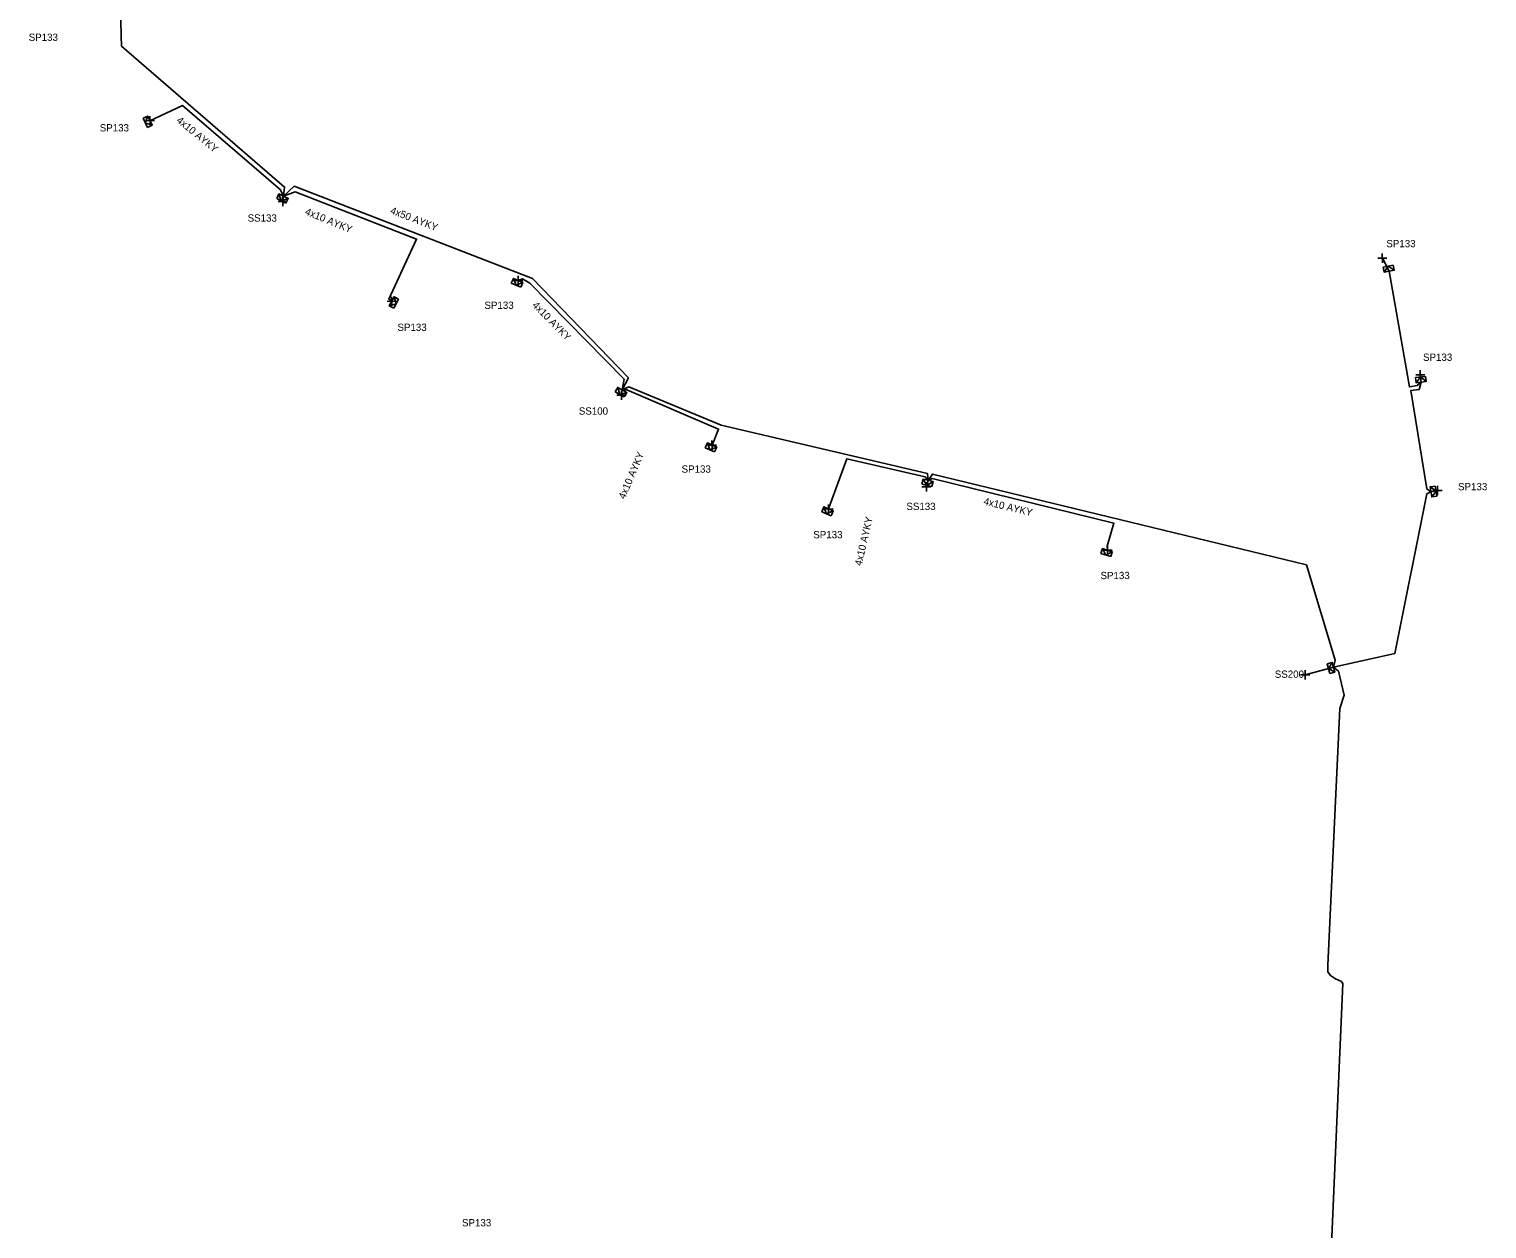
# Model space of a CAD drawing. Extents: x -762503 to -762212, y -1153994 to -1153331.
# Drawn here: x -762411.4 to -762212.4, y -1153826.1 to -1153662.2 of the extents above; entities that cross this region are included whole.
import ezdxf

# ---------------------------------------------------------------- set-up
doc = ezdxf.new("R2010")
doc.units = 0
for name, color, linetype in [('Vrstva 31', 7, 'Continuous'), ('Vrstva 33', 7, 'Continuous'), ('Vrstva 34', 7, 'Continuous'), ('Vrstva 5', 7, 'Continuous'), ('Vrstva 52', 7, 'Continuous'), ('Vrstva 54', 7, 'Continuous'), ('Vrstva 59', 7, 'Continuous'), ('Vrstva 6', 7, 'Continuous')]:
    doc.layers.add(name, color=color, linetype=linetype)

msp = doc.modelspace()

# ---------------------------------------------------------------- linework, layer by layer
at = {"layer": 'Vrstva 31'}
for points in [[(-762395.881, -1153674.399), (-762395.247, -1153674.103), (-762394.655, -1153675.372), (-762395.29, -1153675.668)], [(-762395.881, -1153674.399), (-762395.29, -1153675.668)], [(-762395.586, -1153675.034), (-762395.247, -1153674.103)], [(-762395.586, -1153675.034), (-762394.655, -1153675.372)], [(-762377.639, -1153685.382), (-762377.332, -1153684.752), (-762376.073, -1153685.366), (-762376.38, -1153685.995)], [(-762377.01, -1153685.688), (-762377.332, -1153684.752)], [(-762377.639, -1153685.382), (-762376.38, -1153685.995)], [(-762377.01, -1153685.688), (-762376.073, -1153685.366)], [(-762225.139, -1153694.488), (-762226.518, -1153694.732)], [(-762225.139, -1153694.488), (-762225.018, -1153695.178), (-762226.397, -1153695.421), (-762226.518, -1153694.732)], [(-762225.829, -1153694.61), (-762226.397, -1153695.421)], [(-762225.829, -1153694.61), (-762225.018, -1153695.178)], [(-762345.597, -1153696.934), (-762345.312, -1153696.294), (-762344.033, -1153696.864), (-762344.318, -1153697.503)], [(-762345.597, -1153696.934), (-762344.318, -1153697.503)], [(-762344.957, -1153697.219), (-762345.312, -1153696.294)], [(-762344.957, -1153697.219), (-762344.033, -1153696.864)], [(-762361.652, -1153700.37), (-762362.27, -1153700.041), (-762361.612, -1153698.805), (-762360.994, -1153699.134)], [(-762361.652, -1153700.37), (-762360.994, -1153699.134)], [(-762361.323, -1153699.752), (-762361.612, -1153698.805)], [(-762361.323, -1153699.752), (-762362.27, -1153700.041)], [(-762331.405, -1153711.792), (-762331.065, -1153711.18), (-762329.841, -1153711.858), (-762330.18, -1153712.471)], [(-762330.793, -1153712.131), (-762331.065, -1153711.18)], [(-762220.737, -1153709.669), (-762222.127, -1153709.84)], [(-762220.737, -1153709.669), (-762220.652, -1153710.364), (-762222.042, -1153710.535), (-762222.127, -1153709.84)], [(-762221.432, -1153709.755), (-762222.042, -1153710.535)], [(-762221.432, -1153709.755), (-762220.652, -1153710.364)], [(-762331.405, -1153711.792), (-762330.18, -1153712.471)], [(-762330.793, -1153712.131), (-762329.841, -1153711.858)], [(-762319.107, -1153719.413), (-762318.822, -1153718.774), (-762317.543, -1153719.343), (-762317.828, -1153719.983)], [(-762318.467, -1153719.698), (-762318.822, -1153718.774)], [(-762319.107, -1153719.413), (-762317.828, -1153719.983)], [(-762318.467, -1153719.698), (-762317.543, -1153719.343)], [(-762289.513, -1153724.405), (-762289.355, -1153723.723), (-762287.991, -1153724.037), (-762288.148, -1153724.719)], [(-762289.513, -1153724.405), (-762288.148, -1153724.719)], [(-762288.831, -1153724.562), (-762289.355, -1153723.723)], [(-762288.831, -1153724.562), (-762287.991, -1153724.037)], [(-762219.209, -1153726.048), (-762219.902, -1153726.146), (-762220.097, -1153724.759), (-762219.404, -1153724.662)], [(-762219.306, -1153725.355), (-762220.097, -1153724.759)], [(-762219.209, -1153726.048), (-762219.404, -1153724.662)], [(-762219.306, -1153725.355), (-762219.902, -1153726.146)], [(-762303.191, -1153728.16), (-762302.918, -1153727.515), (-762301.629, -1153728.062), (-762301.902, -1153728.707)], [(-762303.191, -1153728.16), (-762301.902, -1153728.707)], [(-762302.547, -1153728.433), (-762302.918, -1153727.515)], [(-762302.547, -1153728.433), (-762301.629, -1153728.062)], [(-762265.065, -1153733.869), (-762264.849, -1153733.203), (-762263.518, -1153733.636), (-762263.734, -1153734.302)], [(-762265.065, -1153733.869), (-762263.734, -1153734.302)], [(-762264.4, -1153734.085), (-762264.849, -1153733.203)], [(-762264.4, -1153734.085), (-762263.518, -1153733.636)], [(-762234.169, -1153748.923), (-762233.492, -1153748.741), (-762233.13, -1153750.094), (-762233.806, -1153750.275)], [(-762234.169, -1153748.923), (-762233.806, -1153750.275)], [(-762233.987, -1153749.599), (-762233.492, -1153748.741)], [(-762233.987, -1153749.599), (-762233.13, -1153750.094)]]:
    msp.add_lwpolyline(points, dxfattribs=at)
at = {"layer": 'Vrstva 34'}
for points in [[(-762395.575, -1153674.751), (-762394.325, -1153674.729)], [(-762394.939, -1153675.365), (-762394.961, -1153674.115)], [(-762376.819, -1153686.415), (-762376.841, -1153685.165)], [(-762377.455, -1153685.801), (-762376.205, -1153685.779)], [(-762226.629, -1153694.155), (-762226.651, -1153692.905)], [(-762227.265, -1153693.541), (-762226.015, -1153693.519)], [(-762345.295, -1153696.591), (-762344.045, -1153696.569)], [(-762344.659, -1153697.205), (-762344.681, -1153695.955)], [(-762361.929, -1153700.045), (-762361.951, -1153698.795)], [(-762362.565, -1153699.431), (-762361.315, -1153699.409)], [(-762221.449, -1153710.075), (-762221.471, -1153708.825)], [(-762222.085, -1153709.461), (-762220.835, -1153709.439)], [(-762331.185, -1153712.261), (-762329.935, -1153712.239)], [(-762330.549, -1153712.875), (-762330.571, -1153711.625)], [(-762318.805, -1153719.071), (-762317.555, -1153719.049)], [(-762318.169, -1153719.685), (-762318.191, -1153718.435)], [(-762289.535, -1153724.771), (-762288.285, -1153724.749)], [(-762288.899, -1153725.385), (-762288.921, -1153724.135)], [(-762219.099, -1153725.885), (-762219.121, -1153724.635)], [(-762219.735, -1153725.271), (-762218.485, -1153725.249)], [(-762302.895, -1153727.801), (-762301.645, -1153727.779)], [(-762302.259, -1153728.415), (-762302.281, -1153727.165)], [(-762264.169, -1153734.045), (-762264.191, -1153732.795)], [(-762264.805, -1153733.431), (-762263.555, -1153733.409)], [(-762237.805, -1153750.451), (-762236.555, -1153750.429)], [(-762237.169, -1153751.065), (-762237.191, -1153749.815)]]:
    msp.add_lwpolyline(points, dxfattribs=at)
at = {"layer": 'Vrstva 5'}
for points in [[(-762401.37, -1153614.46), (-762400.57, -1153614.41), (-762399.68, -1153614.77), (-762399.13, -1153648.45), (-762403.85, -1153648.67), (-762404.43, -1153648.85), (-762403.69, -1153649.01), (-762399.2, -1153648.85), (-762398.88, -1153663.17), (-762398.84, -1153664.54), (-762376.56, -1153683.82), (-762376.7, -1153685.06), (-762375.27, -1153683.69), (-762342.71, -1153696.28), (-762329.6, -1153709.89), (-762330.45, -1153711.52), (-762329.56, -1153711.08), (-762316.93, -1153716.36), (-762288.76, -1153722.92), (-762288.67, -1153723.88), (-762288.09, -1153723.01), (-762237.01, -1153735.42), (-762233.07, -1153748.45), (-762233.31, -1153749.42)], [(-762220, -1153725.45), (-762220.54, -1153725.04), (-762222.76, -1153711.61), (-762221.61, -1153711.48), (-762221.35, -1153710.45), (-762221.87, -1153710.94), (-762222.93, -1153711.12), (-762225.71, -1153695.3)], [(-762233.31, -1153749.42), (-762224.93, -1153747.51), (-762220.54, -1153725.71), (-762220, -1153725.45)], [(-762233.31, -1153749.42), (-762232.64, -1153749.94), (-762231.83, -1153753.24), (-762232.45, -1153755.06), (-762234.08, -1153790.12), (-762234.08, -1153791.01), (-762233.73, -1153791.54), (-762233.02, -1153791.98), (-762232.22, -1153792.34), (-762232.05, -1153792.6), (-762234.26, -1153844.02)]]:
    msp.add_lwpolyline(points, dxfattribs=at)
at = {"layer": 'Vrstva 52'}
for points in [[(-762376.7, -1153685.06), (-762377.14, -1153684.18), (-762390.51, -1153672.65), (-762394.95, -1153674.74)], [(-762376.7, -1153685.06), (-762375.14, -1153684.44), (-762358.53, -1153690.91), (-762362.34, -1153699.12), (-762361.94, -1153699.42)], [(-762330.45, -1153711.52), (-762330.18, -1153710.06), (-762343.07, -1153696.94), (-762344.09, -1153696.36), (-762344.67, -1153696.58)], [(-762330.45, -1153711.52), (-762329.83, -1153711.52), (-762317.29, -1153716.88), (-762318.18, -1153719.06)], [(-762288.67, -1153723.88), (-762289.07, -1153723.4), (-762299.79, -1153720.92), (-762302.27, -1153727.79)], [(-762288.67, -1153723.88), (-762288.14, -1153723.62), (-762263.29, -1153729.74), (-762264.22, -1153732.89), (-762264.18, -1153733.42)]]:
    msp.add_lwpolyline(points, dxfattribs=at)
at = {"layer": 'Vrstva 59'}
for points in [[(-762376.7, -1153685.06), (-762376.83, -1153685.79)], [(-762225.71, -1153695.3), (-762226.64, -1153693.53)], [(-762221.35, -1153710.45), (-762221.46, -1153709.45)], [(-762330.45, -1153711.52), (-762330.56, -1153712.25)], [(-762288.67, -1153723.88), (-762288.91, -1153724.76)], [(-762220, -1153725.45), (-762219.11, -1153725.26)], [(-762233.31, -1153749.42), (-762237.18, -1153750.44)]]:
    msp.add_lwpolyline(points, dxfattribs=at)

# ---------------------------------------------------------------- texts
at = {"layer": 'Vrstva 33'}
for s, p in [('SP133', (-762411.51, -1153663.84)), ('SP133', (-762401.81, -1153676.21)), ('SS133', (-762381.61, -1153688.53)), ('SP133', (-762226.09, -1153692.03)), ('SP133', (-762349.27, -1153700.45)), ('SP133', (-762361.15, -1153703.46)), ('SP133', (-762221.08, -1153707.55)), ('SS100', (-762336.38, -1153714.9)), ('SP133', (-762322.34, -1153722.83)), ('SP133', (-762216.3, -1153725.23)), ('SS133', (-762291.64, -1153727.93)), ('SP133', (-762304.36, -1153731.79)), ('SP133', (-762265.13, -1153737.37)), ('SS200', (-762241.33, -1153750.85)), ('SP133', (-762352.33, -1153825.79))]:
    msp.add_text(s, height=0.9943, dxfattribs=at).set_placement(p)
at = {"layer": 'Vrstva 54'}
for rotation, p in [(320.65401, (-762391.41, -1153674.85)), (337.61573, (-762373.87, -1153687.52)), (314.49565, (-762342.81, -1153700.03)), (66.83849, (-762330.1, -1153726.52)), (346.17266, (-762281.17, -1153727.16)), (76.96363, (-762297.76, -1153735.61))]:
    msp.add_text('4x10 AYKY', height=0.9943, rotation=rotation, dxfattribs=at).set_placement(p)
at = {"layer": 'Vrstva 6'}
msp.add_text('4x50 AYKY', height=0.9943, rotation=338.86227, dxfattribs=at).set_placement((-762362.21, -1153687.39))

doc.saveas('drawing.dxf')
